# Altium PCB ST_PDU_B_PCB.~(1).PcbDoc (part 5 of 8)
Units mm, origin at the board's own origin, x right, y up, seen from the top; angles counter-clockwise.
Board outline 200 x 200 mm, 6 copper layers (Top Layer, Layer 1, Layer 2, Layer 3, Layer 4, Bottom Layer), stack 3.194 mm thick; 894 components, 723 nets, 3233 pads, 4067 vias.
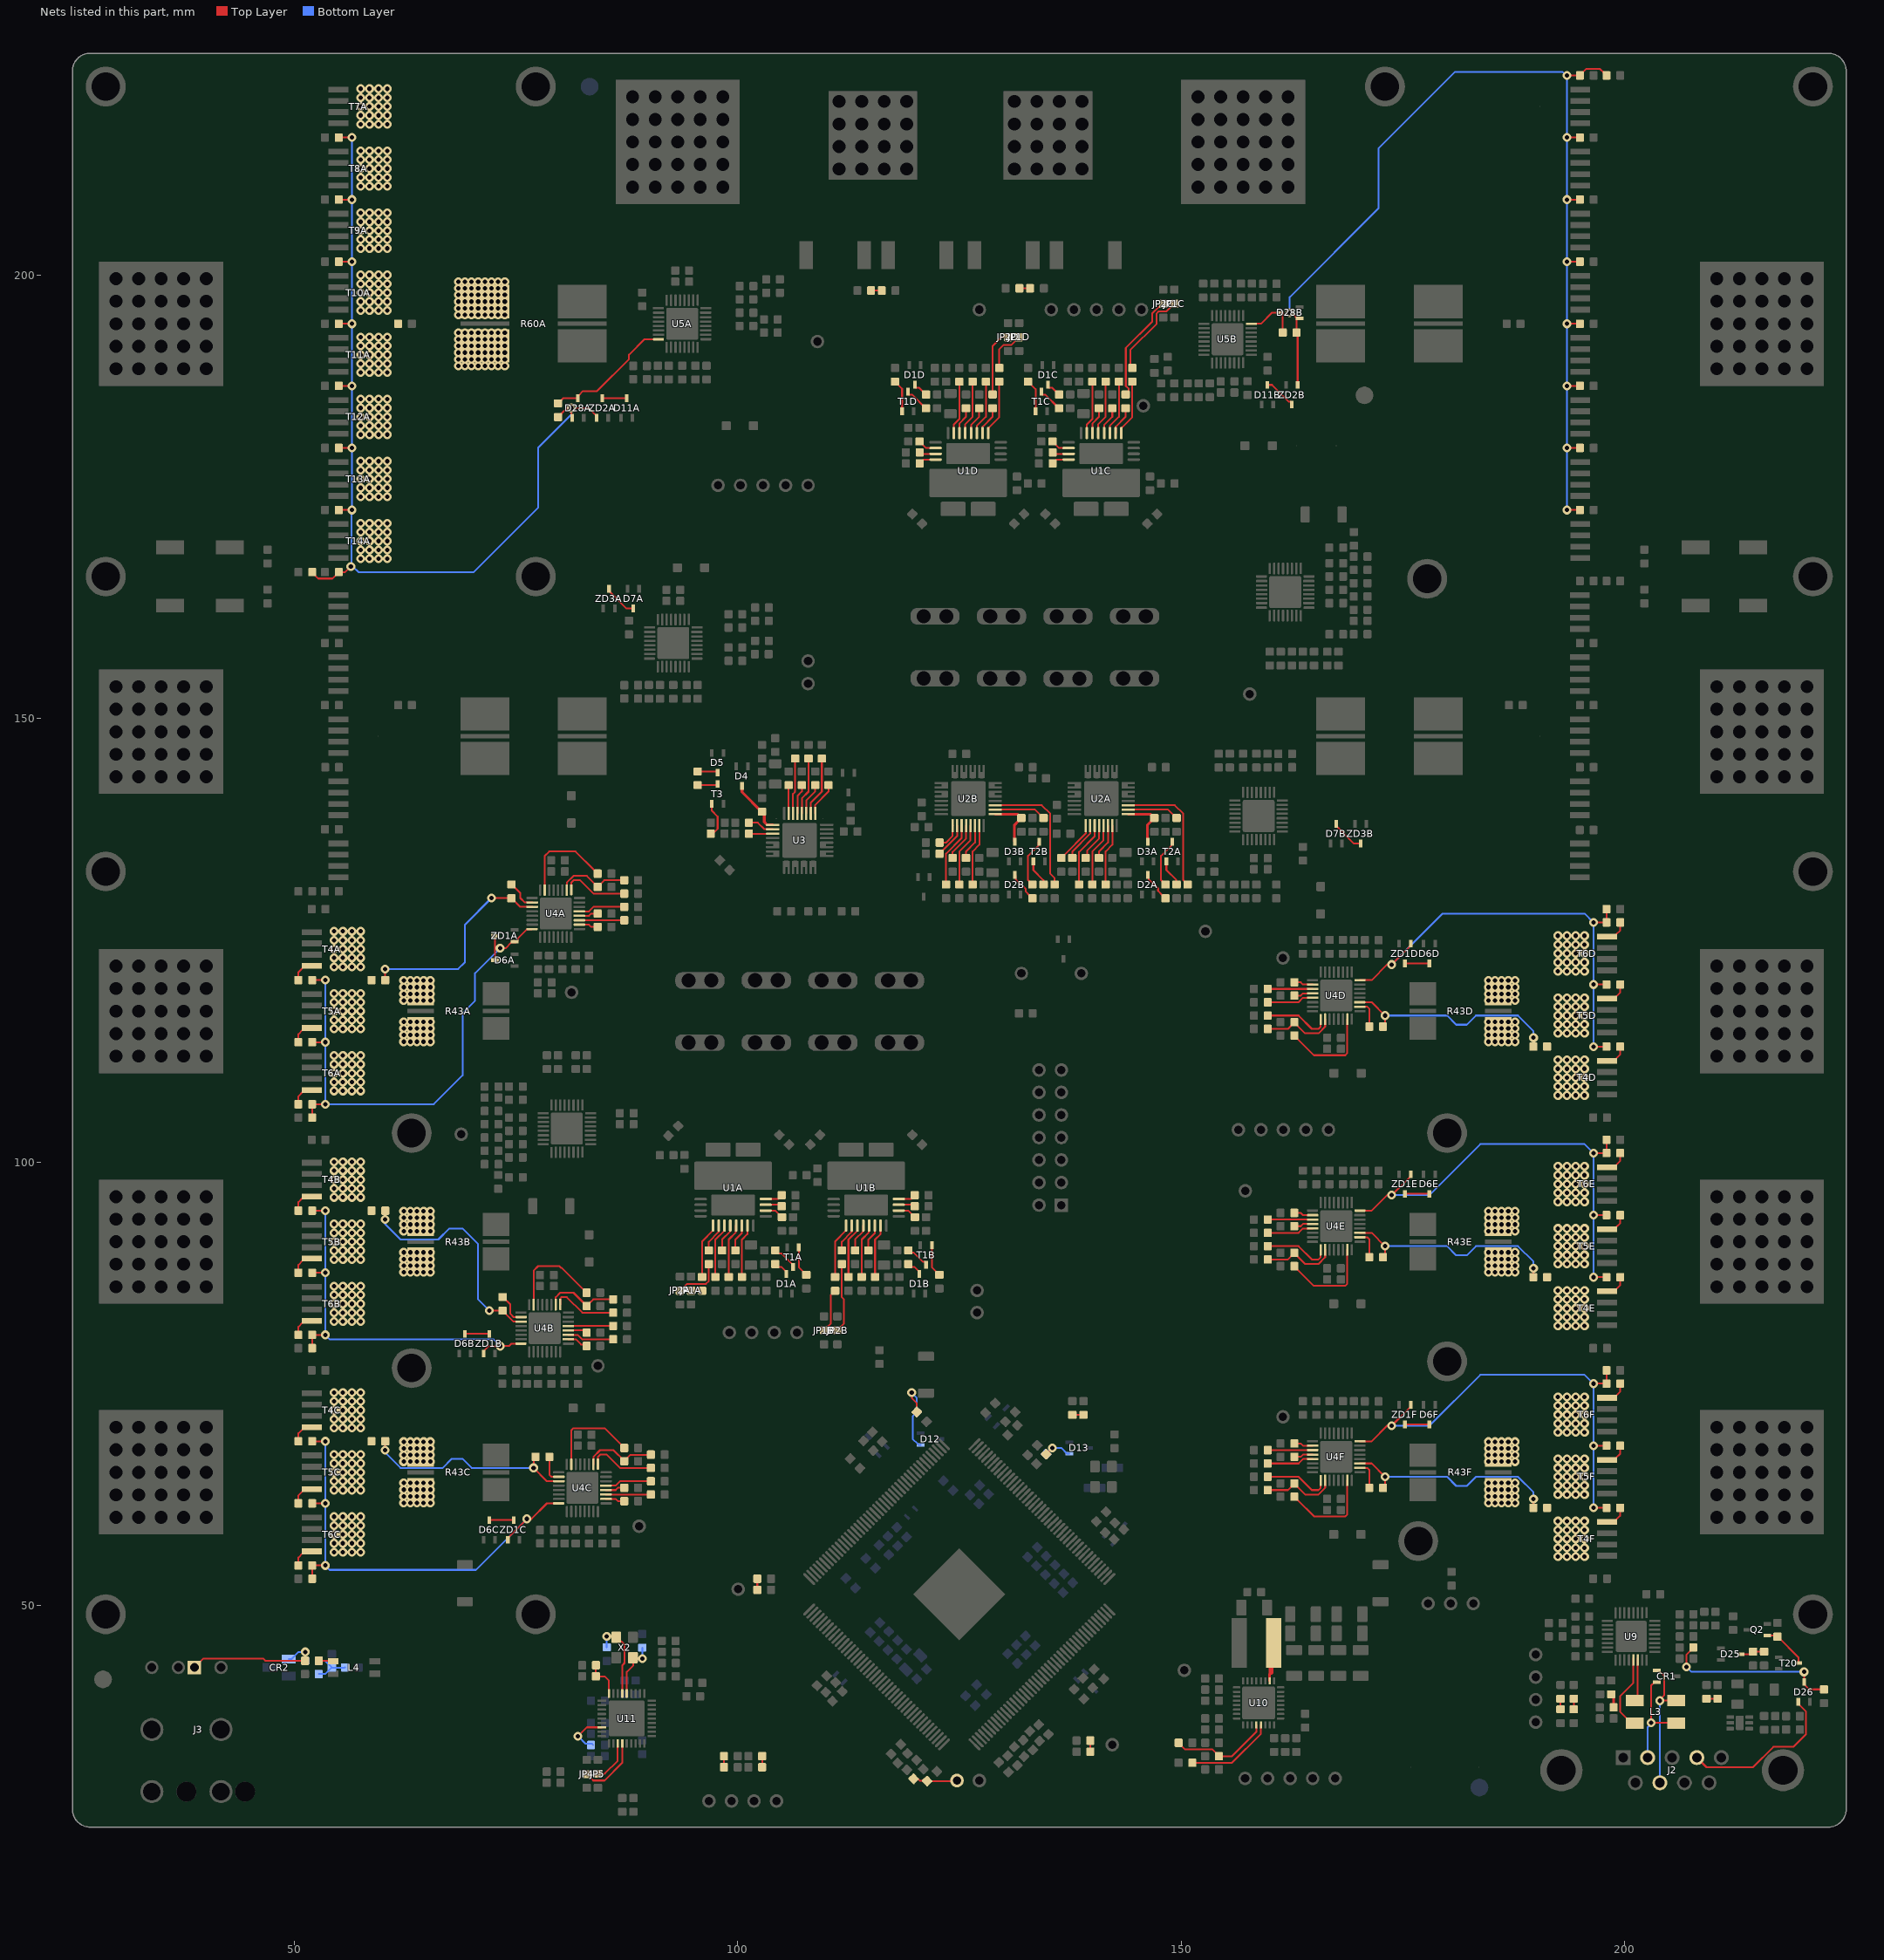
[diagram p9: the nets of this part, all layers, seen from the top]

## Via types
v1: diameter 0.65/1/1/1/1/0.65 (per signal layer), hole 0.5, Top Layer to Bottom Layer, 3739 vias
v2: diameter 0.65/1/1/1/1/0.65 (per signal layer), hole 0.5, Top Layer to Bottom Layer, tented both sides, 296 vias
v3: diameter 0.65, hole 0.5, Top Layer to Bottom Layer, 32 vias

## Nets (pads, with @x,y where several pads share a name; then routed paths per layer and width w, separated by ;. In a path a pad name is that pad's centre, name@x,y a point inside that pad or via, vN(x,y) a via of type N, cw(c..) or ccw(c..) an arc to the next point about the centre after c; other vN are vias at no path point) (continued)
NetC112_1: C112.1 L4.3 | length 1.6
  Top Layer w0.2: C112.1@52.775,43.75 54.35,43.75 L4.3@54.4,43.7
NetC112_2: C112.2 CR2.1 J3.1 R177.1 | length 17.2
  Top Layer w0.2: J3.1@38.75,43 39.754,44.004 46.496,44.004 46.75,43.75 50.245,43.75 ; 50.248,43.748 C112.2@51.225,43.75 C112.2@51.225,43.75 51.25,43.775 v1(51.25,44.75)
  Bottom Layer w0.2: CR2.1@49.384,43.94 49.684,43.94 50.494,44.75 v1(51.25,44.75) 51.25,43.775 R177.1@51.225,43.75
NetC113_2: C113.2 U11.16 | length 5.2
  Top Layer w0.2: v1(82,35.25) 83,36.25 U11.16@84.683,36.25
  Bottom Layer w0.2: v1(82,35.25) 82.842,34.408 83.567,34.408 C113.2@83.725,34.25
NetC117_2: C117.2 R177.2 R178.2 R183.2 | length 5
  Bottom Layer w0.2: R178.2@52.775,42.25 53.5,42.25 C117.2@54.225,42.975 ; R177.2@52.775,43.75 53.5,43.75 54.225,43.025 C117.2@54.225,43 ; C117.2@54.25,42.975 55.7,42.975 R183.2@55.725,43
NetC119_2: C119.2 R187.1 U11.9 | length 4
  Top Layer w0.2: R187.1@84.025,43.25 C119.2@84.025,42 85,42 85.5,41.5 U11.9@85.5,40.45
NetC120_2: C120.2 U11.5 X2.3 | length 6.2
  Top Layer w0.2: U11.5@87.5,40.45 87.5,42.5 88.25,43.25 X2.3@88.25,44.05 ; X2.3@88.2,44.1 X2.3@88.25,44.05 ; v1(89.25,44) 88.3,44 X2.3@88.25,44.05
  Bottom Layer w0.2: v1(89.25,44) C120.2@89.25,45.225
NetC121_2: C121.2 U11.6 X2.1 | length 8.6
  Top Layer w0.2: v1(85.25,46.5) 86.2,46.5 X2.1@86.3,46.4 ; X2.1@86.55,46.3 87.25,45.6 87.25,43.5 87,43.25 U11.6@87,40.45
  Bottom Layer w0.2: C121.2@85.25,45.275 v1(85.25,46.5)
NetC122_1: C122.1 C124.2 | length 1.6
  Top Layer w0.3: C122.1@198.5,39.975 198.775,39.7 C124.2@198.775,38.5
NetCR1_1: CR1.1 J2.7 L3.4 | length 15.2
  Top Layer w0.2: CR1.1@203.642,42.65 203.874,42.65 204.5,42.024 204.5,39.872 204,39.372 v1(204,39.25) 205.83,39.25 L3.4@205.85,39.27
  Bottom Layer w0.2: J2.7@204,30 v1(204,39.25)
NetCR1_2: CR1.2 J2.2 L3.1 | length 11.9
  Top Layer w0.2: CR1.2@203.642,41.35 203.409,41.35 203,40.941 v1(203,36.75) 205.83,36.75 L3.1@205.85,36.73
  Bottom Layer w0.2: J2.2@202.615,32.84 202.615,36.251 203,36.636 v1(203,36.75)
NetD1A_C: D1A.3 R3A.1 | length 1.8
  Top Layer w0.2: R3A.1@104.25,88.475 104.592,88.133 104.958,88.133 105.5,87.591 D1A.3@105.5,87.358
NetD1B_C: D1B.3 R3B.1 | length 1.8
  Top Layer w0.2: R3B.1@119.25,88.475 119.592,88.133 119.958,88.133 120.5,87.591 D1B.3@120.5,87.358
NetD1C_C: D1C.3 R3C.1 | length 1.8
  Top Layer w0.2: D1C.3@135,187.642 135,187.409 135.103,187.306 135.444,187.306 136.225,186.525 R3C.1@136.25,186.525
NetD1D_C: D1D.3 R3D.1 | length 1.8
  Top Layer w0.2: D1D.3@120,187.642 120,187.409 120.103,187.306 120.444,187.306 121.225,186.525 R3D.1@121.25,186.525
NetD2A_C: D2A.3 R17A.1 | length 3.5
  Top Layer w0.2: D2A.3@146.25,132.358 146.353,132.255 146.353,131.897 147.416,130.834 147.416,130.559 147.883,130.092 147.883,130.074 148.232,129.725 R17A.1@148.25,129.725
NetD2B_C: D2B.3 R17B.1 | length 3.5
  Top Layer w0.2: D2B.3@131.25,132.358 131.353,132.255 131.353,131.897 132.5,130.75 132.5,130.475 132.883,130.092 132.883,130.074 133.232,129.725 R17B.1@133.25,129.725
NetD3A_3: D3A.3 R28A.1 U2A.17 | length 6.1
  Top Layer w0.3: U2A.17@144.057,139.214 146.536,139.214 R28A.1@146.975,138.775 ; D3A.3@146.25,136.108 146.225,136.133 146.225,138.025 R28A.1@146.975,138.775 ; R28A.1@147,138.775 R28A.1@146.975,138.775
NetD3B_3: D3B.3 R28B.1 U2B.17 | length 6.1
  Top Layer w0.3: U2B.17@129.057,139.214 131.536,139.214 R28B.1@131.975,138.775 ; D3B.3@131.25,136.108 131.225,136.133 131.225,138 131.675,138.45 131.675,138.475 R28B.1@131.975,138.775 ; R28B.1@132,138.775 R28B.1@131.975,138.775
NetD4_3: D4.3 R42.1 U3.17 | length 6.2
  Top Layer w0.3: D4.3@100.5,142.392 100.5,141.7 102.725,139.475 R42.1@102.75,139.475 103.013,139.212 103.013,138.321 103.333,138 U3.17@103.956,138
NetD5_C: D5.3 R31.1 | length 2.3
  Top Layer w0.2: R31.1@95.5,144.025 97.647,144.025 97.75,143.922 D5.3@97.75,143.892
NetD6A_C: D6A.3 ZD1A.3 | length 2.7
  Top Layer w0.2: D6A.3@72.642,122.75 ZD1A.3@72.642,125.5
NetD6B_C: D6B.3 ZD1B.3 | length 2.7
  Top Layer w0.2: D6B.3@69.25,80.608 ZD1B.3@72,80.608
NetD6C_C: D6C.3 ZD1C.3 | length 2.7
  Top Layer w0.2: D6C.3@72,59.608 ZD1C.3@74.75,59.608
NetD6D_C: D6D.3 ZD1D.3 | length 2.7
  Top Layer w0.2: ZD1D.3@175.25,122.392 D6D.3@178,122.392
NetD6E_C: D6E.3 ZD1E.3 | length 2.7
  Top Layer w0.2: ZD1E.3@175.25,96.392 D6E.3@178,96.392
NetD6F_C: D6F.3 ZD1F.3 | length 2.7
  Top Layer w0.2: ZD1F.3@175.25,70.392 D6F.3@178,70.392
NetD7A_C: D7A.3 ZD3A.3 | length 3.8
  Top Layer w0.2: ZD3A.3@85.5,164.608 85.5,164.376 87.485,162.392 D7A.3@88.25,162.392
NetD7B_C: D7B.3 ZD3B.3 | length 3.8
  Top Layer w0.2: D7B.3@167.5,138.108 167.5,137.876 169.485,135.892 ZD3B.3@170.25,135.892
NetD11A_C: D11A.3 ZD2A.3 | length 3.5
  Top Layer w0.2: ZD2A.3@84.75,186.108 D11A.3@87.5,186.108 86.735,186.108
NetD11B_C: D11B.3 ZD2B.3 | length 3.8
  Top Layer w0.2: D11B.3@159.75,187.608 160.252,187.608 162.153,185.707 162.397,185.707 162.5,185.604 ZD2B.3@162.5,185.392
NetD12_A: D12.1 R122.2 R123.2 | length 9.3
  Top Layer w0.2: v1(119.63,73.984) 119.647,73.968 119.647,73.359 120.22,72.786 120.22,71.816 R123.2@120.202,71.798
  Bottom Layer w0.2: v1(119.63,73.984) 120.22,73.395 120.22,71.816 R122.2@120.202,71.798 120.202,71.772 119.75,71.32 119.75,68.759 120.306,68.203 120.409,68.1 D12.1@120.642,68.1
NetD13_A: D13.1 R128.2 R130.2 | length 4.2
  Top Layer w0.2: R130.2@134.798,67.048 v1(135.5,67.75)
  Bottom Layer w0.2: R128.2@134.787,67.059 134.809,67.059 v1(135.5,67.75) 136.509,67.75 137.159,67.1 D13.1@137.392,67.1
NetD25_3: D25.3 R171.2 R172.2 | length 2.8
  Top Layer w0.2: D25.3@213.108,44.5 214.225,44.5 R172.2@214.5,44.775 R171.2@215.75,44.775
NetD26_1: D26.1 J2.4 | length 18.3
  Top Layer w0.2: J2.4@208.155,32.84 209.25,31.745 214.486,31.745 216.791,34.05 219.038,34.05 220.475,35.487 220.475,38.034 219.6,38.909 D26.1@219.6,39.142
NetD26_3: D26.3 R160.2 R203.2 | length 19.9
  Top Layer w0.2: v1(207,43.05) 207,44.45 207.775,45.225 R160.2@207.775,45.25 ; v1(220.25,42.5) D26.3@220.25,41.358 220.25,41.126 220.851,40.525 R203.2@222.5,40.525
  Bottom Layer w0.2: v1(207,43.05) 207.55,42.5 v1(220.25,42.5)
NetD28A_A: D28A.1 R61A.1 R62A.1 R63A.1 R64A.1 R66A.1 R72A.1 R74A.1 R79A.1 R81A.1 R206A.2 ZD2A.1 | length 107.9
  Top Layer w0.2: R64A.1@52.025,166.5 52.025,166.475 52.725,165.775 54.325,165.775 55.025,166.475 R81A.1@55.025,166.5 55.75,166.5 v1(56.393,167.143) ; R79A.1@55.025,173.5 v1(56.5,173.5) ; R74A.1@55.025,180.5 v1(56.5,180.5) ; R72A.1@55.025,187.5 v1(56.5,187.5) ; R66A.1@55.025,194.5 v1(56.5,194.5) ; R63A.1@55.025,201.5 v1(56.5,201.5) ; R62A.1@55.025,208.5 v1(56.5,208.5) ; R61A.1@55.025,215.5 v1(56.5,215.5) ; R206A.2@79.75,183.975 79.768,183.975 80.117,184.324 80.117,184.342 80.771,184.996 81.246,184.996 v1(81.25,185) ; D28A.1@81.251,183.99 81.251,184.999 v1(81.25,185) ; D28A.1@81.266,183.975 D28A.1@81.35,183.891 ; D28A.1@81.35,183.975 D28A.1@81.35,184.124 ; ZD2A.1@84.1,183.892 84.1,184.124 83.997,184.227 83.224,185 v1(81.25,185)
  Bottom Layer w0.2: v1(56.393,167.143) v1@56.5,167.25 ; v1(56.5,215.5) v1(56.5,208.5) v1(56.5,201.5) v1(56.5,194.5) v1(56.5,187.5) v1(56.5,180.5) v1(56.5,173.5) 56.446,173.446 56.446,167.304 v1@56.5,167.25 ; v1(81.25,185) 81.25,184.25 77.5,180.5 77.5,173.75 70.25,166.5 57.25,166.5 56.693,167.057 56.601,167.057 56.5,167.158 v1@56.5,167.25
NetD28A_C: D28A.3 R206A.1 U5A.24 | length 14.6
  Top Layer w0.2: R206A.1@79.75,185.525 79.768,185.525 80.117,185.874 80.117,185.892 80.333,186.108 D28A.3@82,186.108 ; D28A.3@81.953,186.29 81.953,186.294 82.103,186.444 82.107,186.444 82.563,186.9 84.15,186.9 87.75,190.5 87.75,191 89.5,192.75 U5A.24@91.073,192.75
NetD28B_A: D28B.1 R61B.1 R62B.1 R63B.1 R64B.1 R66B.1 R72B.1 R74B.1 R79B.1 R81B.1 R206B.2 ZD2B.1 | length 121
  Top Layer w0.2: v1(162.25,195.75) 162.336,195.664 162.562,195.664 163.126,195.1 D28B.1@163.358,195.1 ; D28B.1@163.128,195.1 163.025,194.997 R206B.2@163.025,193.5 163.15,193.375 ZD2B.1@163.15,187.608 ; v1(193.5,173.5) R61B.1@194.975,173.5 ; v1(193.5,180.5) R62B.1@194.975,180.5 ; v1(193.5,187.5) R63B.1@194.975,187.5 ; v1(193.5,194.5) R66B.1@194.975,194.5 ; v1(193.5,201.5) R72B.1@194.975,201.5 ; v1(193.5,208.5) R74B.1@194.975,208.5 ; v1(193.5,215.5) R79B.1@194.975,215.5 ; v1(193.5,222.5) R81B.1@194.975,222.5 194.975,222.525 195.675,223.225 197.25,223.225 197.608,222.867 197.626,222.867 197.975,222.518 R64B.1@197.975,222.5
  Bottom Layer w0.2: v1(162.25,195.75) 162.25,197.5 172.25,207.5 172.25,214.25 180.9,222.9 193.016,222.9 193.416,222.5 v1(193.5,222.5) 193.5,215.522 v1(193.5,173.5)
NetD28B_C: D28B.3 R206B.1 U5B.24 | length 6.3
  Top Layer w0.2: U5B.24@157.927,194.5 159.004,194.5 160.254,195.75 D28B.3@161.142,195.75 161.372,195.75 161.475,195.647 R206B.1@161.475,193.5
NetJP1A_1: JP1A.1 R8A.2 | length 1.3
  Top Layer w0.2: JP1A.1@94.75,85.475 R8A.2@96,85.475
NetJP1B_1: JP1B.1 R8B.2 | length 5
  Top Layer w0.2: JP1B.1@109.75,81 109.768,81 110.117,81.349 110.117,81.367 110.5,81.75 110.5,84.975 110.633,85.108 110.633,85.126 110.982,85.475 R8B.2@111,85.475
NetJP1C_1: JP1C.1 R8C.2 | length 9.9
  Top Layer w0.2: R8C.2@144.5,189.525 144.275,189.75 144.275,191.525 147.25,194.5 147.25,195.663 147.487,195.9 148.375,195.9 149.225,196.75 JP1C.1@149.25,196.75
NetJP1D_1: JP1D.1 R8D.2 | length 4.9
  Top Layer w0.2: R8D.2@129.5,189.525 129.5,191.638 129.987,192.125 130.875,192.125 131.725,192.975 JP1D.1@131.75,192.975
NetJP2A_1: JP2A.1 R9A.2 | length 5.6
  Top Layer w0.2: JP2A.1@93.5,85.475 93.525,85.475 94.3,86.25 96.438,86.25 96.75,86.562 R9A.2@96.75,88.475
NetJP2B_1: JP2B.1 R9B.2 | length 7.9
  Top Layer w0.2: JP2B.1@111.25,81.025 111.268,81.025 111.617,81.374 111.617,81.392 112,81.775 112,84.5 111.725,84.775 111.725,88.45 R9B.2@111.75,88.475
NetJP2C_1: JP2C.1 R9C.2 | length 12.4
  Top Layer w0.2: R9C.2@143.75,186.525 143.755,186.525 144.105,186.874 144.105,187.158 143.775,187.487 143.775,191.775 146.75,194.75 146.75,195.658 147.5,196.408 147.658,196.408 JP2C.1@148,196.75
NetJP2D_1: JP2D.1 R9D.2 | length 7.6
  Top Layer w0.2: R9D.2@128.75,186.525 128.75,192 129.725,192.975 JP2D.1@130.5,192.975
NetJP4_1: JP4.1 U11.22 | length 6.9
  Top Layer w0.2: JP4.1@83,30.975 83.018,30.975 83.367,30.626 83.367,30.608 83.725,30.25 85,30.25 87,32.25 U11.22@87,34.05
NetJP5_1: JP5.1 U11.21 | length 4.4
  Top Layer w0.2: JP5.1@84.25,31.025 85.025,31.025 86.481,32.481 86.481,34.031 U11.21@86.5,34.05
NetJP6_1: JP6.1 R169.1 R179.1 | length 5
  Top Layer w0.2: R179.1@119.848,30.44 120.332,30.44 120.564,30.208 121.35,30.208 R169.1@121.372,30.186 121.385,30.173 124.653,30.173 JP6.1@124.73,30.25
NetL1_1: L1.1 U10.2 | length 4.5
  Top Layer w0.3: U10.2@160,41.477 160,42.25 160.155,42.405
  Top Layer w0.5: 160.155,42.405 160.155,45.455 L1.1@160.45,45.75
NetL3_2: L3.2 U9.29 | length 8.8
  Top Layer w0.2: U9.29@201,44.023 201,41.25 199.5,39.75 199.5,37.999 200.77,36.73 L3.2@201.151,36.73
NetL3_3: L3.3 U9.30 | length 4.9
  Top Layer w0.2: L3.3@201.151,39.27 201.5,39.62 U9.30@201.5,44.023
NetLED1_A: LED1.A R138.2 | length 1.3
  Top Layer w0.2: LED1.A@139.775,33.5 R138.2@139.775,34.75
NetLED2_A: LED2.A R142.2 | length 1.3
  Top Layer w0.2: R142.2@102.225,51.75 LED2.A@102.225,53
NetLED3_A: LED3.A R190.1 | length 1.2
  Top Layer w0.2: R190.1@115.05,198.25 LED3.A@116.25,198.25
NetLED4_A: LED4.A R191.1 | length 1.2
  Top Layer w0.2: LED4.A@131.775,198.5 R191.1@132.975,198.5
NetLED5_A: LED5.A R192.2 | length 1.2
  Top Layer w0.2: LED5.A@194.31,38.354 R192.2@194.31,39.554
NetLED6_A: LED6.A R193.1 | length 1.2
  Top Layer w0.2: LED6.A@192.786,38.354 R193.1@192.786,39.554
NetLED7_A: LED7.A R194.1 | length 1.3
  Top Layer w0.2: LED7.A@209.25,39.475 R194.1@210.5,39.475
NetLED8_A: LED8.A R195.2 | length 1.3
  Top Layer w0.2: R195.2@98.467,31.75 LED8.A@98.467,33
NetLED9_A: LED9.A R196.2 | length 1.3
  Top Layer w0.2: R196.2@102.767,31.75 LED9.A@102.767,33
NetLED10_C: LED10.C R202.2 | length 1.3
  Top Layer w0.2: LED10.C@137.75,71.475 R202.2@139,71.475
NetQ2_1: Q2.1 R173.1 T20.3 | length 5.2
  Top Layer w0.2: Q2.1@216.108,46.6 217.125,46.6 R173.1@217.25,46.475 217.275,46.475 219.608,44.142 T20.3@219.608,43.5
NetR3A_2: R3A.2 T1A.3 | length 2.9
  Top Layer w0.2: R3A.2@104.25,90.025 104.592,89.683 104.941,89.683 106.25,88.374 T1A.3@106.25,88.142
NetR3B_2: R3B.2 T1B.3 | length 2.8
  Top Layer w0.2: R3B.2@119.25,90.025 119.508,89.767 119.875,89.767 120.919,88.723 121.147,88.723 121.25,88.62 T1B.3@121.25,88.392
NetR3C_2: R3C.2 T1C.3 | length 2.9
  Top Layer w0.2: T1C.3@134.25,186.858 134.25,186.626 134.353,186.523 134.677,186.523 136.225,184.975 R3C.2@136.25,184.975
NetR3D_2: R3D.2 T1D.3 | length 3
  Top Layer w0.2: T1D.3@119.2,186.858 119.2,186.626 119.303,186.523 119.677,186.523 121.225,184.975 R3D.2@121.25,184.975
NetR4A_2: R4A.2 U1A.2 | length 2.1
  Top Layer w0.2: U1A.2@103.17,94.514 104.236,94.514 104.975,93.775 R4A.2@105,93.775
NetR4B_2: R4B.2 U1B.2 | length 2.1
  Top Layer w0.2: U1B.2@118.17,94.514 119.236,94.514 119.975,93.775 R4B.2@120,93.775
NetR4C_2: R4C.2 U1C.2 | length 2.1
  Top Layer w0.2: R4C.2@135.5,181.225 135.525,181.225 136.264,180.486 U1C.2@137.33,180.486
NetR4D_2: R4D.2 U1D.2 | length 2.1
  Top Layer w0.2: R4D.2@120.5,181.225 120.525,181.225 121.264,180.486 U1D.2@122.33,180.486
NetR5A_1: R5A.1 T1A.1 | length 3.4
  Top Layer w0.2: T1A.1@106.9,90.358 106.9,88.125 107.383,87.642 107.383,87.624 107.732,87.275 R5A.1@107.75,87.275
NetR5B_1: R5B.1 T1B.1 | length 3.4
  Top Layer w0.2: T1B.1@121.9,90.358 121.9,88.125 122.383,87.642 122.383,87.624 122.732,87.275 R5B.1@122.75,87.275
NetR5C_1: R5C.1 T1C.1 | length 3.7
  Top Layer w0.2: R5C.1@132.75,187.975 132.768,187.975 133.117,187.626 133.117,187.608 133.6,187.125 T1C.1@133.6,184.642
NetR5D_1: R5D.1 T1D.1 | length 3.7
  Top Layer w0.2: R5D.1@117.75,187.975 117.768,187.975 118.117,187.626 118.117,187.608 118.55,187.175 T1D.1@118.55,184.642
NetR6A_1: R6A.1 U1A.3 | length 1.9
  Top Layer w0.2: U1A.3@103.17,95.164 104.811,95.164 R6A.1@104.975,95
NetR6B_1: R6B.1 U1B.3 | length 1.9
  Top Layer w0.2: U1B.3@118.17,95.164 119.811,95.164 R6B.1@119.975,95
NetR6C_1: R6C.1 U1C.3 | length 1.9
  Top Layer w0.2: R6C.1@135.525,180 135.689,179.836 U1C.3@137.33,179.836
NetR6D_1: R6D.1 U1D.3 | length 1.9
  Top Layer w0.2: R6D.1@120.525,180 120.689,179.836 U1D.3@122.33,179.836
NetR7A_1: R7A.1 U1A.4 | length 2
  Top Layer w0.2: U1A.4@103.17,95.814 104.557,95.814 104.975,96.232 R7A.1@104.975,96.25
NetR7B_1: R7B.1 U1B.4 | length 2
  Top Layer w0.2: U1B.4@118.17,95.814 119.557,95.814 119.975,96.232 R7B.1@119.975,96.25
NetR7C_1: R7C.1 U1C.4 | length 2
  Top Layer w0.2: R7C.1@135.525,178.75 135.525,178.768 135.943,179.186 U1C.4@137.33,179.186
NetR7D_1: R7D.1 U1D.4 | length 2
  Top Layer w0.2: R7D.1@120.525,178.75 120.525,178.768 120.943,179.186 U1D.4@122.33,179.186
NetR8A_1: R8A.1 U1A.11 | length 6.3
  Top Layer w0.2: R8A.1@96,87.025 96,91.018 97.225,92.243 U1A.11@97.225,92.82
NetR8B_1: R8B.1 U1B.11 | length 6.3
  Top Layer w0.2: R8B.1@111,87.025 111,91.018 112.225,92.243 U1B.11@112.225,92.82
NetR8C_1: R8C.1 U1C.11 | length 6.3
  Top Layer w0.2: U1C.11@143.275,182.18 143.275,182.757 144.5,183.982 R8C.1@144.5,187.975
NetR8D_1: R8D.1 U1D.11 | length 6.3
  Top Layer w0.2: U1D.11@128.275,182.18 128.275,182.757 129.5,183.982 R8D.1@129.5,187.975
NetR9A_1: R9A.1 U1A.12 | length 3.3
  Top Layer w0.2: R9A.1@96.75,90.025 96.75,91 97.856,92.106 97.856,92.801 U1A.12@97.875,92.82
NetR9B_1: R9B.1 U1B.12 | length 3.3
  Top Layer w0.2: R9B.1@111.75,90.025 111.75,91 112.856,92.106 112.856,92.801 U1B.12@112.875,92.82
NetR9C_1: R9C.1 U1C.12 | length 3.3
  Top Layer w0.2: U1C.12@142.625,182.18 142.644,182.199 142.644,182.894 143.75,184 R9C.1@143.75,184.975
NetR9D_1: R9D.1 U1D.12 | length 3.3
  Top Layer w0.2: U1D.12@127.625,182.18 127.644,182.199 127.644,182.894 128.75,184 R9D.1@128.75,184.975
NetR10A_1: R10A.1 U1A.13 | length 6.2
  Top Layer w0.2: R10A.1@97.5,87.025 97.5,91.25 98.526,92.276 U1A.13@98.526,92.82
NetR10B_1: R10B.1 U1B.13 | length 6.2
  Top Layer w0.2: R10B.1@112.5,87.025 112.5,91.25 113.526,92.276 U1B.13@113.526,92.82
NetR10C_1: R10C.1 U1C.13 | length 6.2
  Top Layer w0.2: U1C.13@141.974,182.18 141.974,182.974 143,184 R10C.1@143,187.975
NetR10D_1: R10D.1 U1D.13 | length 6.2
  Top Layer w0.2: U1D.13@126.974,182.18 126.974,182.974 128,184 R10D.1@128,187.975
NetR11A_1: R11A.1 U1A.14 | length 3.2
  Top Layer w0.2: R11A.1@98.25,90.025 98.25,91.25 99.156,92.156 99.156,92.801 U1A.14@99.176,92.82
NetR11B_1: R11B.1 U1B.14 | length 3.2
  Top Layer w0.2: R11B.1@113.25,90.025 113.25,91.255 114.156,92.161 114.156,92.801 U1B.14@114.176,92.82
NetR11C_1: R11C.1 U1C.14 | length 3.2
  Top Layer w0.2: U1C.14@141.325,182.18 141.324,183.074 142.25,184 R11C.1@142.25,184.975
NetR11D_1: R11D.1 U1D.14 | length 3.2
  Top Layer w0.2: U1D.14@126.324,182.18 126.324,183.074 127.25,184 R11D.1@127.25,184.975
NetR12A_1: R12A.1 U1A.15 | length 6.1
  Top Layer w0.2: R12A.1@99,87.025 99,91.25 99.805,92.055 99.805,92.801 U1A.15@99.824,92.82
NetR12B_1: R12B.1 U1B.15 | length 6.1
  Top Layer w0.2: R12B.1@114,87.025 114,91.25 114.805,92.055 114.805,92.801 U1B.15@114.824,92.82
NetR12C_1: R12C.1 U1C.15 | length 6.1
  Top Layer w0.2: U1C.15@140.676,182.18 140.676,183.176 141.5,184 R12C.1@141.5,187.975
NetR12D_1: R12D.1 U1D.15 | length 6.1
  Top Layer w0.2: U1D.15@125.676,182.18 125.676,183.176 126.5,184 R12D.1@126.5,187.975
NetR13A_1: R13A.1 U1A.16 | length 3.1
  Top Layer w0.2: R13A.1@99.75,90.025 99.75,91.25 100.475,91.974 U1A.16@100.475,92.82
NetR13B_1: R13B.1 U1B.16 | length 3.1
  Top Layer w0.2: R13B.1@114.75,90.025 114.75,91.25 115.476,91.976 115.476,92.819 U1B.16@115.475,92.82
NetR13C_1: R13C.1 U1C.16 | length 3.1
  Top Layer w0.2: U1C.16@140.026,182.18 140.024,182.181 140.024,183.274 140.75,184 R13C.1@140.75,184.975
NetR13D_1: R13D.1 U1D.16 | length 3.1
  Top Layer w0.2: U1D.16@125.026,182.18 125.024,182.181 125.024,183.274 125.75,184 R13D.1@125.75,184.975
NetR14A_1: R14A.1 U1A.17 | length 6.1
  Top Layer w0.2: R14A.1@100.5,87.025 100.5,91.25 101.105,91.855 101.105,92.801 U1A.17@101.124,92.82
NetR14B_1: R14B.1 U1B.17 | length 6.1
  Top Layer w0.2: R14B.1@115.5,87.025 115.5,91.25 116.124,91.874 U1B.17@116.124,92.82
NetR14C_1: R14C.1 U1C.17 | length 6.1
  Top Layer w0.2: U1C.17@139.376,182.18 139.376,183.126 140,183.75 R14C.1@140,187.975
NetR14D_1: R14D.1 U1D.17 | length 6.1
  Top Layer w0.2: U1D.17@124.376,182.18 124.376,183.126 125,183.75 R14D.1@125,187.975
NetR17A_2: R17A.2 T2A.3 | length 5.6
  Top Layer w0.2: R17A.2@148.25,131.275 148.232,131.275 147.883,131.624 147.883,131.642 147.75,131.775 147.75,134.5 148.897,135.647 148.897,136.005 T2A.3@149,136.108
NetR17B_2: R17B.2 T2B.3 | length 5.6
  Top Layer w0.2: R17B.2@133.25,131.275 133.232,131.275 132.883,131.624 132.883,131.642 132.75,131.775 132.75,134.5 133.897,135.647 133.897,136.005 T2B.3@134,136.108
NetR18A_2: R18A.2 U2A.18 | length 5.8
  Top Layer w0.2: U2A.18@144.057,139.714 148.536,139.714 149.475,138.775 R18A.2@149.5,138.775
NetR18B_2: R18B.2 U2B.18 | length 5.8
  Top Layer w0.2: U2B.18@129.057,139.714 133.536,139.714 134.475,138.775 R18B.2@134.5,138.775
NetR19A_1: R19A.1 T2A.1 | length 3.1
  Top Layer w0.2: T2A.1@148.35,133.892 148.35,132.9 149.475,131.775 149.475,131.3 R19A.1@149.5,131.275
NetR19B_1: R19B.1 T2B.1 | length 3.1
  Top Layer w0.2: T2B.1@133.35,133.892 133.35,132.9 134.5,131.75 R19B.1@134.5,131.275
NetR20A_1: R20A.1 U2A.9 | length 4.8
  Top Layer w0.2: R20A.1@136.509,134.275 136.518,134.275 136.875,134.632 136.875,134.641 139.263,137.029 U2A.9@139.263,137.921
NetR20B_1: R20B.1 U2B.9 | length 3
  Top Layer w0.2: R20B.1@122.775,136 123.5,136 124.25,136.75 124.25,137.908 U2B.9@124.263,137.921
NetR21A_1: R21A.1 U2A.10 | length 4.5
  Top Layer w0.2: R21A.1@137.75,134.275 137.75,135 139.763,137.013 U2A.10@139.763,137.921
NetR21B_1: R21B.1 U2B.10 | length 4
  Top Layer w0.2: R21B.1@122.775,134.75 122.775,134.768 123.124,135.117 123.142,135.117 124.763,136.738 U2B.10@124.763,137.921
NetR22A_1: R22A.1 U2A.11 | length 7.4
  Top Layer w0.2: R22A.1@138.5,131.275 138.5,134.949 140.263,136.712 U2A.11@140.263,137.921
NetR22B_1: R22B.1 U2B.11 | length 7.4
  Top Layer w0.2: R22B.1@123.5,131.275 123.5,134.75 125.263,136.513 U2B.11@125.263,137.921
NetR23A_1: R23A.1 U2A.19 | length 14.8
  Top Layer w0.2: U2A.19@144.057,140.215 149.285,140.215 150.25,139.25 150.25,131.775 150.383,131.642 150.383,131.624 150.732,131.275 R23A.1@150.75,131.275
NetR23B_1: R23B.1 U2B.19 | length 14.8
  Top Layer w0.2: U2B.19@129.057,140.215 134.285,140.215 135.25,139.25 135.25,132.5 135.75,132 R23B.1@135.75,131.275
NetR24A_1: R24A.1 U2A.12 | length 4.3
  Top Layer w0.2: R24A.1@139.25,134.275 139.408,134.433 139.408,135.102 140.763,136.457 U2A.12@140.763,137.921
NetR24B_1: R24B.1 U2B.12 | length 4.3
  Top Layer w0.2: R24B.1@124.25,134.275 124.25,134.944 125.763,136.457 U2B.12@125.763,137.921
NetR25A_1: R25A.1 U2A.13 | length 7.2
  Top Layer w0.2: R25A.1@140,131.275 140,135 141.264,136.263 U2A.13@141.264,137.921
NetR25B_1: R25B.1 U2B.13 | length 7.2
  Top Layer w0.2: R25B.1@125,131.275 125,135 126.264,136.263 U2B.13@126.264,137.921
NetR26A_1: R26A.1 U2A.14 | length 4.1
  Top Layer w0.2: R26A.1@140.75,134.275 140.75,135 141.764,136.014 U2A.14@141.764,137.921
NetR26B_1: R26B.1 U2B.14 | length 4.1
  Top Layer w0.2: R26B.1@125.75,134.275 125.75,135 126.764,136.014 U2B.14@126.764,137.921
NetR27A_1: R27A.1 U2A.15 | length 7
  Top Layer w0.2: R27A.1@141.5,131.275 141.5,135 142.264,135.764 U2A.15@142.264,137.921
NetR27B_1: R27B.1 U2B.15 | length 7
  Top Layer w0.2: R27B.1@126.5,131.275 126.5,135 127.264,135.764 U2B.15@127.264,137.921
NetR31_2: R31.2 T3.3 | length 2.3
  Top Layer w0.2: R31.2@95.5,142.475 97.647,142.475 97.75,142.578 T3.3@97.75,142.608
NetR32_2: R32.2 U3.18 | length 3
  Top Layer w0.2: R32.2@101.275,138.25 102.275,138.25 102.998,137.527 103.929,137.527 U3.18@103.956,137.5
NetR33_1: R33.1 T3.1 | length 3.9
  Top Layer w0.2: T3.1@97.1,140.392 97.1,139.588 97.75,138.938 97.75,137.55 R33.1@97.225,137.025
NetR34_1: R34.1 U3.9 | length 3.8
  Top Layer w0.2: U3.9@108.75,139.294 108.75,140.25 110.25,141.75 R34.1@110.25,142.475
NetR35_1: R35.1 U3.10 | length 6.7
  Top Layer w0.2: U3.10@108.25,139.294 108.25,140.5 109.5,141.75 R35.1@109.5,145.475
NetR36_1: R36.1 U3.11 | length 3.6
  Top Layer w0.2: U3.11@107.75,139.294 107.75,140.757 108.75,141.757 R36.1@108.75,142.475
NetR37_1: R37.1 U3.19 | length 2.4
  Top Layer w0.2: R37.1@101.525,137 U3.19@103.956,137
NetR38_1: R38.1 U3.12 | length 6.5
  Top Layer w0.2: U3.12@107.25,139.294 107.25,141 108,141.75 R38.1@108,145.475
NetR39_1: R39.1 U3.13 | length 3.4
  Top Layer w0.2: U3.13@106.75,139.294 106.75,141.257 107.25,141.757 R39.1@107.25,142.475
NetR40_1: R40.1 U3.14 | length 6.3
  Top Layer w0.2: U3.14@106.25,139.294 106.25,141.5 106.5,141.75 R40.1@106.5,145.475
NetR41_1: R41.1 U3.15 | length 3.2
  Top Layer w0.2: U3.15@105.75,139.294 R41.1@105.75,142.475
NetR43A_1: R43A.1 R54A.2 T4A.D T5A.D T6A.D
  other v1: 54.5,108 55.5,108 56.5,108 57.5,108 54.5,109 55.5,109 56.5,109 57.5,109 54.5,110 55.5,110 56.5,110 57.5,110 54.5,111 55.5,111 56.5,111 57.5,111 54.5,112 55.5,112 56.5,112 57.5,112 63.1,114.3 63.85,114.3 64.6,114.3 65.35,114.3 54.5,115 55.5,115 56.5,115 57.5,115 63.1,115.05 63.85,115.05 64.6,115.05 65.35,115.05 63.1,115.8 63.85,115.8 64.6,115.8 65.35,115.8 54.5,116 55.5,116 56.5,116 57.5,116 54.5,117 55.5,117 56.5,117 57.5,117 54.5,118 55.5,118 56.5,118 57.5,118 63.1,118.2 63.85,118.2 64.6,118.2 65.35,118.2 63.1,118.95 63.85,118.95 64.6,118.95 65.35,118.95 54.5,119 55.5,119 56.5,119 57.5,119 63.1,119.7 63.85,119.7 64.6,119.7 65.35,119.7 54.5,122 55.5,122 56.5,122 57.5,122 54.5,123 55.5,123 56.5,123 57.5,123 54.5,124 55.5,124 56.5,124 57.5,124 54.5,125 55.5,125 56.5,125 57.5,125 54.5,126 55.5,126 56.5,126 57.5,126
  other v2: 62.35,113.55 63.1,113.55 63.85,113.55 64.6,113.55 65.35,113.55 62.35,114.3 62.35,115.05 62.35,115.8 62.35,118.2 62.35,118.95 62.35,119.7 62.35,120.45 63.1,120.45 63.85,120.45 64.6,120.45 65.35,120.45
NetR43B_1: R43B.1 R54B.2 T4B.D T5B.D T6B.D
  other v1: 54.5,82 55.5,82 56.5,82 57.5,82 54.5,83 55.5,83 56.5,83 57.5,83 54.5,84 55.5,84 56.5,84 57.5,84 54.5,85 55.5,85 56.5,85 57.5,85 54.5,86 55.5,86 56.5,86 57.5,86 63.1,88.3 63.85,88.3 64.6,88.3 65.35,88.3 54.5,89 55.5,89 56.5,89 57.5,89 63.1,89.05 63.85,89.05 64.6,89.05 65.35,89.05 63.1,89.8 63.85,89.8 64.6,89.8 65.35,89.8 54.5,90 55.5,90 56.5,90 57.5,90 54.5,91 55.5,91 56.5,91 57.5,91 54.5,92 55.5,92 56.5,92 57.5,92 63.1,92.2 63.85,92.2 64.6,92.2 65.35,92.2 63.1,92.95 63.85,92.95 64.6,92.95 65.35,92.95 54.5,93 55.5,93 56.5,93 57.5,93 63.1,93.7 63.85,93.7 64.6,93.7 65.35,93.7 54.5,96 55.5,96 56.5,96 57.5,96 54.5,97 55.5,97 56.5,97 57.5,97 54.5,98 55.5,98 56.5,98 57.5,98 54.5,99 55.5,99 56.5,99 57.5,99 54.5,100 55.5,100 56.5,100 57.5,100
  other v2: 62.35,87.55 63.1,87.55 63.85,87.55 64.6,87.55 65.35,87.55 62.35,88.3 62.35,89.05 62.35,89.8 62.35,92.2 62.35,92.95 62.35,93.7 62.35,94.45 63.1,94.45 63.85,94.45 64.6,94.45 65.35,94.45
NetR43C_1: R43C.1 R54C.2 T4C.D T5C.D T6C.D
  other v1: 54.5,56 55.5,56 56.5,56 57.5,56 54.5,57 55.5,57 56.5,57 57.5,57 54.5,58 55.5,58 56.5,58 57.5,58 54.5,59 55.5,59 56.5,59 57.5,59 54.5,60 55.5,60 56.5,60 57.5,60 63.1,62.3 63.85,62.3 64.6,62.3 65.35,62.3 54.5,63 55.5,63 56.5,63 57.5,63 63.1,63.05 63.85,63.05 64.6,63.05 65.35,63.05 63.1,63.8 63.85,63.8 64.6,63.8 65.35,63.8 54.5,64 55.5,64 56.5,64 57.5,64 54.5,65 55.5,65 56.5,65 57.5,65 54.5,66 55.5,66 56.5,66 57.5,66 63.1,66.2 63.85,66.2 64.6,66.2 65.35,66.2 63.1,66.95 63.85,66.95 64.6,66.95 65.35,66.95 54.5,67 55.5,67 56.5,67 57.5,67 63.1,67.7 63.85,67.7 64.6,67.7 65.35,67.7 54.5,70 55.5,70 56.5,70 57.5,70 54.5,71 55.5,71 56.5,71 57.5,71 54.5,72 55.5,72 56.5,72 57.5,72 54.5,73 55.5,73 56.5,73 57.5,73 54.5,74 55.5,74 56.5,74 57.5,74
  other v2: 62.35,61.55 63.1,61.55 63.85,61.55 64.6,61.55 65.35,61.55 62.35,62.3 62.35,63.05 62.35,63.8 62.35,66.2 62.35,66.95 62.35,67.7 62.35,68.45 63.1,68.45 63.85,68.45 64.6,68.45 65.35,68.45
NetR43D_1: R43D.1 R54D.2 T4D.D T5D.D T6D.D
  other v1: 192.5,107.5 193.5,107.5 194.5,107.5 195.5,107.5 192.5,108.5 193.5,108.5 194.5,108.5 195.5,108.5 192.5,109.5 193.5,109.5 194.5,109.5 195.5,109.5 192.5,110.5 193.5,110.5 194.5,110.5 195.5,110.5 192.5,111.5 193.5,111.5 194.5,111.5 195.5,111.5 184.65,114.3 185.4,114.3 186.15,114.3 186.9,114.3 192.5,114.5 193.5,114.5 194.5,114.5 195.5,114.5 184.65,115.05 185.4,115.05 186.15,115.05 186.9,115.05 192.5,115.5 193.5,115.5 194.5,115.5 195.5,115.5 184.65,115.8 185.4,115.8 186.15,115.8 186.9,115.8 192.5,116.5 193.5,116.5 194.5,116.5 195.5,116.5 192.5,117.5 193.5,117.5 194.5,117.5 195.5,117.5 184.65,118.2 185.4,118.2 186.15,118.2 186.9,118.2 192.5,118.5 193.5,118.5 194.5,118.5 195.5,118.5 184.65,118.95 185.4,118.95 186.15,118.95 186.9,118.95 184.65,119.7 185.4,119.7 186.15,119.7 186.9,119.7 192.5,121.5 193.5,121.5 194.5,121.5 195.5,121.5 192.5,122.5 193.5,122.5 194.5,122.5 195.5,122.5 192.5,123.5 193.5,123.5 194.5,123.5 195.5,123.5 192.5,124.5 193.5,124.5 194.5,124.5 195.5,124.5 192.5,125.5 193.5,125.5 194.5,125.5 195.5,125.5
  other v2: 184.65,113.55 185.4,113.55 186.15,113.55 186.9,113.55 187.65,113.55 187.65,114.3 187.65,115.05 187.65,115.8 187.65,118.2 187.65,118.95 187.65,119.7 184.65,120.45 185.4,120.45 186.15,120.45 186.9,120.45 187.65,120.45
NetR43E_1: R43E.1 R54E.2 T4E.D T5E.D T6E.D
  other v1: 192.5,81.5 193.5,81.5 194.5,81.5 195.5,81.5 192.5,82.5 193.5,82.5 194.5,82.5 195.5,82.5 192.5,83.5 193.5,83.5 194.5,83.5 195.5,83.5 192.5,84.5 193.5,84.5 194.5,84.5 195.5,84.5 192.5,85.5 193.5,85.5 194.5,85.5 195.5,85.5 184.65,88.3 185.4,88.3 186.15,88.3 186.9,88.3 192.5,88.5 193.5,88.5 194.5,88.5 195.5,88.5 184.65,89.05 185.4,89.05 186.15,89.05 186.9,89.05 192.5,89.5 193.5,89.5 194.5,89.5 195.5,89.5 184.65,89.8 185.4,89.8 186.15,89.8 186.9,89.8 192.5,90.5 193.5,90.5 194.5,90.5 195.5,90.5 192.5,91.5 193.5,91.5 194.5,91.5 195.5,91.5 184.65,92.2 185.4,92.2 186.15,92.2 186.9,92.2 192.5,92.5 193.5,92.5 194.5,92.5 195.5,92.5 184.65,92.95 185.4,92.95 186.15,92.95 186.9,92.95 184.65,93.7 185.4,93.7 186.15,93.7 186.9,93.7 192.5,95.5 193.5,95.5 194.5,95.5 195.5,95.5 192.5,96.5 193.5,96.5 194.5,96.5 195.5,96.5 192.5,97.5 193.5,97.5 194.5,97.5 195.5,97.5 192.5,98.5 193.5,98.5 194.5,98.5 195.5,98.5 192.5,99.5 193.5,99.5 194.5,99.5 195.5,99.5
  other v2: 184.65,87.55 185.4,87.55 186.15,87.55 186.9,87.55 187.65,87.55 187.65,88.3 187.65,89.05 187.65,89.8 187.65,92.2 187.65,92.95 187.65,93.7 184.65,94.45 185.4,94.45 186.15,94.45 186.9,94.45 187.65,94.45
NetR43F_1: R43F.1 R54F.2 T4F.D T5F.D T6F.D
  other v1: 192.5,55.5 193.5,55.5 194.5,55.5 195.5,55.5 192.5,56.5 193.5,56.5 194.5,56.5 195.5,56.5 192.5,57.5 193.5,57.5 194.5,57.5 195.5,57.5 192.5,58.5 193.5,58.5 194.5,58.5 195.5,58.5 192.5,59.5 193.5,59.5 194.5,59.5 195.5,59.5 184.65,62.3 185.4,62.3 186.15,62.3 186.9,62.3 192.5,62.5 193.5,62.5 194.5,62.5 195.5,62.5 184.65,63.05 185.4,63.05 186.15,63.05 186.9,63.05 192.5,63.5 193.5,63.5 194.5,63.5 195.5,63.5 184.65,63.8 185.4,63.8 186.15,63.8 186.9,63.8 192.5,64.5 193.5,64.5 194.5,64.5 195.5,64.5 192.5,65.5 193.5,65.5 194.5,65.5 195.5,65.5 184.65,66.2 185.4,66.2 186.15,66.2 186.9,66.2 192.5,66.5 193.5,66.5 194.5,66.5 195.5,66.5 184.65,66.95 185.4,66.95 186.15,66.95 186.9,66.95 184.65,67.7 185.4,67.7 186.15,67.7 186.9,67.7 192.5,69.5 193.5,69.5 194.5,69.5 195.5,69.5 192.5,70.5 193.5,70.5 194.5,70.5 195.5,70.5 192.5,71.5 193.5,71.5 194.5,71.5 195.5,71.5 192.5,72.5 193.5,72.5 194.5,72.5 195.5,72.5 192.5,73.5 193.5,73.5 194.5,73.5 195.5,73.5
  other v2: 184.65,61.55 185.4,61.55 186.15,61.55 186.9,61.55 187.65,61.55 187.65,62.3 187.65,63.05 187.65,63.8 187.65,66.2 187.65,66.95 187.65,67.7 184.65,68.45 185.4,68.45 186.15,68.45 186.9,68.45 187.65,68.45
NetR44A_1: R44A.1 R45A.1 R47A.2 R53A.1 U4A.24 ZD1A.1 | length 57.5
  Top Layer w0.2: R45A.1@52.025,105 R53A.1@52.025,106.5 v1(53.5,106.5) ; R47A.2@52.025,113.5 v1(53.5,113.5) ; R44A.1@52.025,120.5 v1(53.5,120.5) ; v1(73.217,124.086) 73.222,124.092 73.842,124.092 74.497,124.747 74.987,124.747 75.194,124.953 75.194,125.161 76.255,126.223 76.796,126.223 U4A.24@76.823,126.25
  Bottom Layer w0.2: v1(53.5,120.5) v1(53.5,113.5) v1(53.5,106.5) 65.75,106.5 69,109.75 69,116.76 70.404,118.164 70.404,121.274 v1(73.217,124.086)
NetR44A_2: R44A.2 T4A.G | length 2.7
  Top Layer w0.2: R44A.2@50.475,120.5 50.475,121.392 51.178,122.095 T4A.G@51.978,122.095
NetR44B_1: R44B.1 R45B.1 R47B.2 R53B.1 U4B.24 ZD1B.1 | length 45
  Top Layer w0.2: R45B.1@52.025,79 R53B.1@52.025,80.5 v1(53.5,80.5) ; R47B.2@52.025,87.5 v1(53.5,87.5) ; R44B.1@52.025,94.5 v1(53.5,94.5) ; ZD1B.1@71.35,78.392 71.35,78.624 71.95,79.223 v1(73.245,79.223) ; v1@73.25,79.25 74.25,79.25 74.5,79.5 U4B.24@75.573,79.5
  Bottom Layer w0.2: v1(53.5,94.5) v1(53.5,87.5) v1(53.5,80.5) 54,80 72.468,80 v1(73.245,79.223)
NetR44B_2: R44B.2 T4B.G | length 2.7
  Top Layer w0.2: R44B.2@50.475,94.5 50.475,95.475 50.87,95.87 51.753,95.87 T4B.G@51.978,96.095
NetR44C_1: R44C.1 R45C.1 R47C.2 R53C.1 U4C.24 ZD1C.1 | length 52.8
  Top Layer w0.2: R45C.1@52.025,53 R53C.1@52.025,54.5 v1(53.5,54.5) ; R47C.2@52.025,61.5 v1(53.5,61.5) ; R44C.1@52.025,68.5 v1(53.5,68.5) ; ZD1C.1@74.1,57.392 74.1,57.624 74.203,57.727 74.227,57.727 v1(76.25,59.75) 76.75,59.75 78.5,61.5 U4C.24@79.823,61.5
  Bottom Layer w0.2: v1(53.5,68.5) v1(53.5,61.5) v1(53.5,54.5) 54,54 70.5,54 v1(76.25,59.75)
NetR44C_2: R44C.2 T4C.G | length 2.7
  Top Layer w0.2: R44C.2@50.475,68.5 50.475,69.392 51.178,70.095 T4C.G@51.978,70.095
NetR44D_1: R44D.1 R45D.1 R47D.2 R53D.1 U4D.24 ZD1D.1 | length 53
  Top Layer w0.2: U4D.24@170.177,120.5 171.5,120.5 173.25,122.25 v1(173.75,122.25) 175.773,124.273 175.797,124.273 175.9,124.376 ZD1D.1@175.9,124.608 ; v1(196.5,113) R44D.1@197.975,113 ; v1(196.5,120) R47D.2@197.975,120 ; v1(196.5,127) R53D.1@197.975,127 R45D.1@197.975,128.5
  Bottom Layer w0.2: v1(173.75,122.25) 179.5,128 195.5,128 v1(196.5,127) v1(196.5,120) v1(196.5,113)
NetR44D_2: R44D.2 T4D.G | length 2.7
  Top Layer w0.2: T4D.G@198.022,111.405 198.822,111.405 199.5,112.083 199.5,112.975 R44D.2@199.525,113
NetR44E_1: R44E.1 R45E.1 R47E.2 R53E.1 U4E.24 ZD1E.1 | length 53
  Top Layer w0.2: U4E.24@170.177,94.5 171.5,94.5 173.25,96.25 v1(173.75,96.25) 175.773,98.273 175.797,98.273 175.9,98.376 ZD1E.1@175.9,98.608 ; v1(196.5,87) R44E.1@197.975,87 ; v1(196.5,94) R47E.2@197.975,94 ; v1(196.5,101) R53E.1@197.975,101 R45E.1@197.975,102.5
  Bottom Layer w0.2: v1(173.75,96.25) 178,96.25 183.75,102 195.5,102 v1(196.5,101) v1(196.5,94) v1(196.5,87)
NetR44E_2: R44E.2 T4E.G | length 2.7
  Top Layer w0.2: T4E.G@198.022,85.405 198.822,85.405 199.047,85.63 199.525,86.108 R44E.2@199.525,87
NetR44F_1: R44F.1 R45F.1 R47F.2 R53F.1 U4F.24 ZD1F.1 | length 53
  Top Layer w0.2: U4F.24@170.177,68.5 171.5,68.5 173.25,70.25 v1(173.75,70.25) 175.773,72.273 175.797,72.273 175.9,72.376 ZD1F.1@175.9,72.608 ; v1(196.5,61) R44F.1@197.975,61 ; v1(196.5,68) R47F.2@197.975,68 ; v1(196.5,75) R53F.1@197.975,75 R45F.1@197.975,76.5
  Bottom Layer w0.2: v1(173.75,70.25) 178,70.25 183.75,76 195.5,76 v1(196.5,75) v1(196.5,68) v1(196.5,61)
NetR44F_2: R44F.2 T4F.G | length 2.7
  Top Layer w0.2: T4F.G@198.022,59.405 198.822,59.405 199.5,60.083 199.5,60.975 R44F.2@199.525,61
NetR46_1: R46.1 R168.2 U10.20 | length 11.3
  Top Layer w0.2: R168.2@149.725,34.5 149.725,34.475 150.45,33.75 153.55,33.75 154.275,33.025 R46.1@154.275,33 155.75,33 158.5,35.75 U10.20@158.5,36.523
NetR47A_1: R47A.1 T5A.G | length 2.7
  Top Layer w0.2: R47A.1@50.475,113.5 50.475,114.392 50.953,114.87 51.178,115.095 T5A.G@51.978,115.095
NetR47B_1: R47B.1 T5B.G | length 2.7
  Top Layer w0.2: R47B.1@50.475,87.5 50.475,88.392 50.953,88.87 51.178,89.095 T5B.G@51.978,89.095
NetR47C_1: R47C.1 T5C.G | length 2.7
  Top Layer w0.2: R47C.1@50.475,61.5 50.475,62.392 50.953,62.87 51.178,63.095 T5C.G@51.978,63.095
NetR47D_1: R47D.1 T5D.G | length 2.7
  Top Layer w0.2: T5D.G@198.022,118.405 198.822,118.405 199.047,118.63 199.525,119.108 R47D.1@199.525,120
NetR47E_1: R47E.1 T5E.G | length 2.7
  Top Layer w0.2: T5E.G@198.022,92.405 198.822,92.405 199.047,92.63 199.525,93.108 R47E.1@199.525,94
NetR47F_1: R47F.1 T5F.G | length 2.7
  Top Layer w0.2: T5F.G@198.022,66.405 198.822,66.405 199.047,66.63 199.525,67.108 R47F.1@199.525,68
NetR48A_1: R48A.1 U4A.2 | length 2.2
  Top Layer w0.2: U4A.2@82.152,126.75 83.25,126.75 83.5,126.5 R48A.1@84.225,126.5
NetR48B_1: R48B.1 U4B.2 | length 2.4
  Top Layer w0.2: U4B.2@80.902,80 81.75,80 82.342,79.408 82.817,79.408 R48B.1@82.975,79.25
NetR48C_1: R48C.1 U4C.2 | length 2.2
  Top Layer w0.2: U4C.2@85.152,62 86.25,62 86.5,61.75 R48C.1@87.225,61.75
NetR48D_1: R48D.1 U4D.2 | length 2.2
  Top Layer w0.2: R48D.1@162.775,120.25 163.5,120.25 163.75,120 U4D.2@164.848,120
NetR48E_1: R48E.1 U4E.2 | length 2.2
  Top Layer w0.2: R48E.1@162.775,94.25 163.5,94.25 163.75,94 U4E.2@164.848,94
NetR48F_1: R48F.1 U4F.2 | length 2.2
  Top Layer w0.2: R48F.1@162.775,68.25 163.5,68.25 163.75,68 U4F.2@164.848,68
NetR49A_1: R49A.1 U4A.3 | length 5.1
  Top Layer w0.2: U4A.3@82.152,127.25 R49A.1@87.225,127.25
NetR49B_1: R49B.1 U4B.3 | length 5.3
  Top Layer w0.2: U4B.3@80.902,80.5 81.97,80.5 82.47,80 R49B.1@85.975,80
NetR49C_1: R49C.1 U4C.3 | length 5.1
  Top Layer w0.2: U4C.3@85.152,62.5 R49C.1@90.225,62.5
NetR49D_1: R49D.1 U4D.3 | length 5.1
  Top Layer w0.2: R49D.1@159.775,119.5 U4D.3@164.848,119.5
NetR49E_1: R49E.1 U4E.3 | length 5.1
  Top Layer w0.2: R49E.1@159.775,93.5 U4E.3@164.848,93.5
NetR49F_1: R49F.1 U4F.3 | length 5.1
  Top Layer w0.2: R49F.1@159.775,67.5 U4F.3@164.848,67.5
NetR50A_2: R50A.2 U4A.4 | length 2.2
  Top Layer w0.2: U4A.4@82.152,127.75 83.25,127.75 83.5,128 R50A.2@84.225,128
NetR50B_2: R50B.2 U4B.4 | length 2.2
  Top Layer w0.2: U4B.4@80.902,81 82.725,81 R50B.2@82.975,80.75
NetR50C_2: R50C.2 U4C.4 | length 2.2
  Top Layer w0.2: U4C.4@85.152,63 86.25,63 86.5,63.25 R50C.2@87.225,63.25
NetR50D_2: R50D.2 U4D.4 | length 2.2
  Top Layer w0.2: R50D.2@162.775,118.75 163.5,118.75 163.75,119 U4D.4@164.848,119
NetR50E_2: R50E.2 U4E.4 | length 2.2
  Top Layer w0.2: R50E.2@162.775,92.75 163.5,92.75 163.75,93 U4E.4@164.848,93
NetR50F_2: R50F.2 U4F.4 | length 2.2
  Top Layer w0.2: R50F.2@162.775,66.75 163.5,66.75 163.75,67 U4F.4@164.848,67
NetR51A_1: R51A.1 U4A.5 | length 5.3
  Top Layer w0.2: U4A.5@82.152,128.25 83.25,128.25 83.75,128.75 R51A.1@87.225,128.75
NetR51B_1: R51B.1 U4B.5 | length 5.2
  Top Layer w0.2: U4B.5@80.902,81.5 R51B.1@86.14,81.5
NetR51C_1: R51C.1 U4C.5 | length 5.3
  Top Layer w0.2: U4C.5@85.152,63.5 86.25,63.5 86.75,64 R51C.1@90.225,64
NetR51D_1: R51D.1 U4D.5 | length 5.3
  Top Layer w0.2: R51D.1@159.775,118 163.25,118 163.75,118.5 U4D.5@164.848,118.5
NetR51E_1: R51E.1 U4E.5 | length 5.3
  Top Layer w0.2: R51E.1@159.775,92 163.25,92 163.75,92.5 U4E.5@164.848,92.5
NetR51F_1: R51F.1 U4F.5 | length 5.3
  Top Layer w0.2: R51F.1@159.775,66 163.25,66 163.75,66.5 U4F.5@164.848,66.5
NetR52_1: R52.1 U10.21 | length 10.1
  Top Layer w0.2: R52.1@151.275,32.25 155.75,32.25 159,35.5 U10.21@159,36.523
NetR53A_2: R53A.2 T6A.G | length 2.7
  Top Layer w0.2: R53A.2@50.475,106.5 50.475,107.392 50.953,107.87 51.178,108.095 T6A.G@51.978,108.095
NetR53B_2: R53B.2 T6B.G | length 2.7
  Top Layer w0.2: R53B.2@50.475,80.5 50.475,81.392 50.953,81.87 51.178,82.095 T6B.G@51.978,82.095
NetR53C_2: R53C.2 T6C.G | length 2.7
  Top Layer w0.2: R53C.2@50.475,54.5 50.475,55.392 50.953,55.87 51.178,56.095 T6C.G@51.978,56.095
NetR53D_2: R53D.2 T6D.G | length 2.7
  Top Layer w0.2: T6D.G@198.022,125.405 198.822,125.405 199.047,125.63 199.525,126.108 R53D.2@199.525,127
NetR53E_2: R53E.2 T6E.G | length 2.7
  Top Layer w0.2: T6E.G@198.022,99.405 198.822,99.405 199.047,99.63 199.525,100.108 R53E.2@199.525,101
NetR53F_2: R53F.2 T6F.G | length 1.6
  Top Layer w0.2: T6F.G@199.047,73.63 199.525,74.108 R53F.2@199.525,75
NetR54A_1: R54A.1 R56A.2 U4A.19 | length 24.1
  Top Layer w0.2: v1(60.25,121.75) 60.25,120.525 R54A.1@60.275,120.5 ; v1(72.25,129.75) 74.475,129.75 R56A.2@74.5,129.725 74.525,129.725 75.5,128.75 U4A.19@76.848,128.75
  Bottom Layer w0.2: v1(60.25,121.75) 68.5,121.75 69.25,122.5 69.25,126.75 v1(72.25,129.75)
NetR54B_1: R54B.1 R56B.2 U4B.19 | length 26.1
  Top Layer w0.2: v1(60.25,93.5) 60.25,94.475 R54B.1@60.275,94.5 ; v1(72,83.25) 73.475,83.25 R56B.2@73.5,83.225 73.518,83.225 73.867,82.876 73.867,82.858 74.725,82 U4B.19@75.598,82
  Bottom Layer w0.2: v1(60.25,93.5) 60.25,93 62,91.25 66.25,91.25 67.5,92.5 69,92.5 70.75,90.75 70.75,84.5 v1(72,83.25)
NetR54C_1: R54C.1 R56C.2 U4C.19 | length 24.4
  Top Layer w0.2: v1(60.25,67.5) 60.25,68.475 R54C.1@60.275,68.5 ; R56C.2@77.25,66.775 R56C.2@77.225,66.75 77,66.525 v1(77,65.5) 78.5,64 U4C.19@79.848,64
  Bottom Layer w0.2: v1(60.25,67.5) 60.336,67.414 60.336,67.164 62,65.5 66.75,65.5 67.78,66.53 68.97,66.53 70,65.5 v1(77,65.5)
NetR54D_1: R54D.1 R56D.2 U4D.19 | length 25.3
  Top Layer w0.2: U4D.19@170.152,118 171.5,118 v1(173,116.5) 173,115.475 R56D.2@172.775,115.25 R56D.2@172.75,115.225 ; R54D.1@189.725,113 189.75,113.025 v1(189.75,114)
  Bottom Layer w0.2: v1(173,116.5) 180,116.5 181.03,115.47 182.22,115.47 183.25,116.5 188,116.5 189.75,114.75 v1(189.75,114) 189.664,114.086 v1@189.664,114.336
NetR54E_1: R54E.1 R56E.2 U4E.19 | length 25.3
  Top Layer w0.2: U4E.19@170.152,92 171.5,92 v1(173,90.5) 173,89.475 R56E.2@172.775,89.25 R56E.2@172.75,89.225 ; R54E.1@189.725,87 189.75,87.025 v1(189.75,88)
  Bottom Layer w0.2: v1(173,90.5) 180,90.5 181.03,89.47 182.22,89.47 183.25,90.5 188,90.5 189.75,88.75 v1(189.75,88) 189.664,88.086 v1@189.664,88.336
NetR54F_1: R54F.1 R56F.2 U4F.19 | length 25.3
  Top Layer w0.2: U4F.19@170.152,66 171.5,66 v1(173,64.5) 173,63.475 R56F.2@172.775,63.25 R56F.2@172.75,63.225 ; R54F.1@189.725,61 189.75,61.025 v1(189.75,62)
  Bottom Layer w0.2: v1(173,64.5) 180,64.5 181.03,63.47 182.22,63.47 183.25,64.5 188,64.5 189.75,62.75 v1(189.75,62) 189.664,62.086 v1@189.664,62.336
NetR55A_2: R55A.2 R58A.1 U4A.10 | length 8.5
  Top Layer w0.2: U4A.10@80.75,130.652 80.75,131.5 81.5,132.25 83,132.25 R55A.2@84.225,131.025 ; R55A.2@84.225,131 R55A.2@84.225,131.025 ; R58A.1@87.225,131.75 84.95,131.75 R55A.2@84.225,131.025
NetR55B_2: R55B.2 R58B.1 U4B.10 | length 8.4
  Top Layer w0.2: U4B.10@79.5,83.902 79.5,84.75 80,85.25 81.5,85.25 82.975,83.775 R55B.2@82.975,83.768 ; R55B.2@82.975,83.75 R55B.2@82.975,83.768 ; R58B.1@85.942,84.5 83.725,84.5 83.342,84.117 83.324,84.117 R55B.2@82.975,83.768
NetR55C_2: R55C.2 R58C.1 U4C.10 | length 8.5
  Top Layer w0.2: U4C.10@83.75,65.902 83.75,66.75 84.5,67.5 86,67.5 R55C.2@87.225,66.275 ; R55C.2@87.225,66.25 R55C.2@87.225,66.275 ; R58C.1@90.225,67 90.2,66.975 87.925,66.975 R55C.2@87.225,66.275
NetR55D_2: R55D.2 R58D.1 U4D.10 | length 8.4
  Top Layer w0.2: R58D.1@159.775,115 162.05,115 162.775,115.725 164,114.5 165.5,114.5 166.25,115.25 U4D.10@166.25,116.098
NetR55E_2: R55E.2 R58E.1 U4E.10 | length 8.5
  Top Layer w0.2: R58E.1@159.775,89 162.05,89 R55E.2@162.775,89.725 ; R55E.2@162.775,89.75 R55E.2@162.775,89.725 ; U4E.10@166.25,90.098 166.25,89.25 165.5,88.5 164,88.5 R55E.2@162.775,89.725
NetR55F_2: R55F.2 R58F.1 U4F.10 | length 8.5
  Top Layer w0.2: R58F.1@159.775,63 162.05,63 R55F.2@162.775,63.725 ; R55F.2@162.775,63.75 R55F.2@162.775,63.725 ; U4F.10@166.25,64.098 166.25,63.25 165.5,62.5 164,62.5 R55F.2@162.775,63.725
NetR56A_1: R56A.1 U4A.18 | length 3.5
  Top Layer w0.2: R56A.1@74.5,131.275 74.525,131.275 75.5,130.3 75.5,129.75 76,129.25 U4A.18@76.848,129.25
NetR56B_1: R56B.1 U4B.18 | length 3.7
  Top Layer w0.2: R56B.1@73.5,84.775 73.525,84.775 74.375,83.925 74.375,82.875 74.75,82.5 U4B.18@75.598,82.5
NetR56C_1: R56C.1 U4C.18 | length 3.2
  Top Layer w0.2: R56C.1@78.775,66.75 78.775,64.725 79,64.5 U4C.18@79.848,64.5
NetR56D_1: R56D.1 U4D.18 | length 3.2
  Top Layer w0.2: U4D.18@170.152,117.5 171,117.5 171.225,117.275 R56D.1@171.225,115.25
NetR56E_1: R56E.1 U4E.18 | length 3.2
  Top Layer w0.2: U4E.18@170.152,91.5 171,91.5 171.225,91.275 R56E.1@171.225,89.25
NetR56F_1: R56F.1 U4F.18 | length 3.2
  Top Layer w0.2: U4F.18@170.152,65.5 171,65.5 171.225,65.275 R56F.1@171.225,63.25
NetR57A_1: R57A.1 U4A.9 | length 7.5
  Top Layer w0.2: U4A.9@81.25,130.677 81.25,131.5 81.5,131.75 82.25,131.75 83.75,130.25 R57A.1@87.225,130.25
NetR57B_1: R57B.1 U4B.9 | length 7.5
  Top Layer w0.2: U4B.9@80,83.927 80.027,83.954 80.027,84.633 80.145,84.75 80.75,84.75 82.5,83 R57B.1@85.975,83 R57B.1@86.038,83
NetR57C_1: R57C.1 U4C.9 | length 7.5
  Top Layer w0.2: U4C.9@84.25,65.927 84.25,66.75 84.5,67 85.25,67 86.75,65.5 R57C.1@90.225,65.5
NetR57D_1: R57D.1 U4D.9 | length 7.5
  Top Layer w0.2: R57D.1@159.775,116.5 163.25,116.5 164.75,115 165.5,115 165.75,115.25 U4D.9@165.75,116.073
NetR57E_1: R57E.1 U4E.9 | length 7.5
  Top Layer w0.2: R57E.1@159.775,90.5 163.25,90.5 164.75,89 165.5,89 165.75,89.25 U4E.9@165.75,90.073
NetR57F_1: R57F.1 U4F.9 | length 7.5
  Top Layer w0.2: R57F.1@159.775,64.5 163.25,64.5 164.75,63 165.5,63 165.75,63.25 U4F.9@165.75,64.073
NetR59A_1: R59A.1 U4A.15 | length 11.1
  Top Layer w0.2: U4A.15@78.25,130.652 78.25,134.488 78.762,135 81.725,135 83.858,132.867 83.876,132.867 84.225,132.518 R59A.1@84.225,132.5
NetR59B_1: R59B.1 U4B.15 | length 11.3
  Top Layer w0.2: U4B.15@77,83.902 77,87.738 77.512,88.25 79.909,88.25 80.123,88.036 80.189,88.036 82.608,85.617 82.626,85.617 82.975,85.268 R59B.1@82.975,85.25
NetR59C_1: R59C.1 U4C.15 | length 10.8
  Top Layer w0.2: U4C.15@81.25,65.902 81.25,69.738 81.487,69.975 85.025,69.975 87.225,67.775 R59C.1@87.225,67.768
NetR59D_1: R59D.1 U4D.15 | length 10.8
  Top Layer w0.2: R59D.1@162.775,114.232 162.775,114.225 164.975,112.025 168.513,112.025 168.75,112.262 U4D.15@168.75,116.098
NetR59E_1: R59E.1 U4E.15 | length 10.8
  Top Layer w0.2: R59E.1@162.775,88.232 162.775,88.225 164.975,86.025 168.513,86.025 168.75,86.262 U4E.15@168.75,90.098
NetR59F_1: R59F.1 U4F.15 | length 10.8
  Top Layer w0.2: R59F.1@162.775,62.25 162.775,62.232 163.124,61.883 163.142,61.883 165,60.025 168.513,60.025 168.75,60.262 U4F.15@168.75,64.098
NetR60A_1: R60A.1 R73A.2 T7A.D T8A.D T9A.D T10A.D T11A.D T12A.D T13A.D T14A.D
  other v1: 57.5,168 58.5,168 59.5,168 60.5,168 57.5,169 58.5,169 59.5,169 60.5,169 57.5,170 58.5,170 59.5,170 60.5,170 57.5,171 58.5,171 59.5,171 60.5,171 57.5,172 58.5,172 59.5,172 60.5,172 57.5,175 58.5,175 59.5,175 60.5,175 57.5,176 58.5,176 59.5,176 60.5,176 57.5,177 58.5,177 59.5,177 60.5,177 57.5,178 58.5,178 59.5,178 60.5,178 57.5,179 58.5,179 59.5,179 60.5,179 57.5,182 58.5,182 59.5,182 60.5,182 57.5,183 58.5,183 59.5,183 60.5,183 57.5,184 58.5,184 59.5,184 60.5,184 57.5,185 58.5,185 59.5,185 60.5,185 57.5,186 58.5,186 59.5,186 60.5,186 57.5,189 58.5,189 59.5,189 60.5,189 57.5,190 58.5,190 59.5,190 60.5,190 69.25,190.5 70,190.5 70.75,190.5 71.5,190.5 72.25,190.5 73,190.5 73.75,190.5 57.5,191 58.5,191 59.5,191 60.5,191 69.25,191.25 70,191.25 70.75,191.25 71.5,191.25 72.25,191.25 73,191.25 73.75,191.25 57.5,192 58.5,192 59.5,192 60.5,192 69.25,192 70,192 70.75,192 71.5,192 72.25,192 73,192 73.75,192 69.25,192.75 70,192.75 70.75,192.75 71.5,192.75 72.25,192.75 73,192.75 73.75,192.75 57.5,193 58.5,193 59.5,193 60.5,193 69.25,193.5 70,193.5 70.75,193.5 71.5,193.5 72.25,193.5 73,193.5 73.75,193.5 69.25,195.5 70,195.5 70.75,195.5 71.5,195.5 72.25,195.5 73,195.5 73.75,195.5 57.5,196 58.5,196 59.5,196 60.5,196 69.25,196.25 70,196.25 70.75,196.25 71.5,196.25 72.25,196.25 73,196.25 73.75,196.25 57.5,197 58.5,197 59.5,197 60.5,197 69.25,197 70,197 70.75,197 71.5,197 72.25,197 73,197 73.75,197 69.25,197.75 70,197.75 70.75,197.75 71.5,197.75 72.25,197.75 73,197.75 73.75,197.75 57.5,198 58.5,198 59.5,198 60.5,198 69.25,198.5 70,198.5 70.75,198.5 71.5,198.5 72.25,198.5 73,198.5 73.75,198.5 57.5,199 58.5,199 59.5,199 60.5,199 57.5,200 58.5,200 59.5,200 60.5,200 57.5,203 58.5,203 59.5,203 60.5,203 57.5,204 58.5,204 59.5,204 60.5,204 57.5,205 58.5,205 59.5,205 60.5,205 57.5,206 58.5,206 59.5,206 60.5,206 57.5,207 58.5,207 59.5,207 60.5,207 57.5,210 58.5,210 59.5,210 60.5,210 57.5,211 58.5,211 59.5,211 60.5,211 57.5,212 58.5,212 59.5,212 60.5,212 57.5,213 58.5,213 59.5,213 60.5,213 57.5,214 58.5,214 59.5,214 60.5,214 57.5,217 58.5,217 59.5,217 60.5,217 57.5,218 58.5,218 59.5,218 60.5,218 57.5,219 58.5,219 59.5,219 60.5,219 57.5,220 58.5,220 59.5,220 60.5,220 57.5,221 58.5,221 59.5,221 60.5,221
  other v2: 68.5,189.75 69.25,189.75 70,189.75 70.75,189.75 71.5,189.75 72.25,189.75 73,189.75 73.75,189.75 68.5,190.5 68.5,191.25 68.5,192 68.5,192.75 68.5,193.5 68.5,195.5 68.5,196.25 68.5,197 68.5,197.75 68.5,198.5 68.5,199.25 69.25,199.25 70,199.25 70.75,199.25 71.5,199.25 72.25,199.25 73,199.25 73.75,199.25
